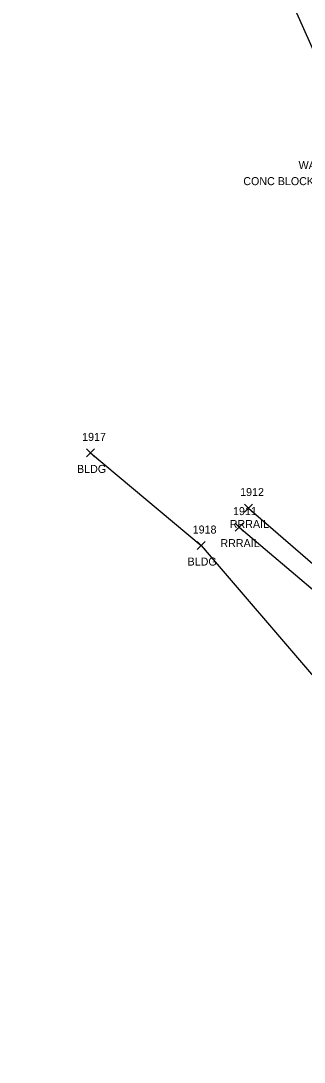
# Model space of a CAD drawing. Extents: x 1635588 to 1637550, y 621583 to 623638.
# Drawn here: x 1636590.6 to 1636661.5, y 622165 to 622425.2 of the extents above; entities that cross this region are included whole.
import ezdxf

# ---------------------------------------------------------------- set-up
doc = ezdxf.new("R2010")
doc.units = 0
for name, color, linetype in [('L_A', 7, 'Continuous'), ('L_C', 7, 'Continuous'), ('L_I', 7, 'Continuous'), ('L_TIC', 7, 'Continuous'), ('LBC', 7, 'Continuous'), ('R_A', 7, 'Continuous'), ('R_I', 7, 'Continuous'), ('R_TIC', 7, 'Continuous'), ('RR', 7, 'Continuous')]:
    doc.layers.add(name, color=color, linetype=linetype)

msp = doc.modelspace()

# ---------------------------------------------------------------- linework, layer by layer
at = {"layer": 'L_TIC'}
for points in [[(1636607.08, 622316.23), (1636609.08, 622318.23)], [(1636609.08, 622316.23), (1636607.08, 622318.23)], [(1636634.72, 622293.09), (1636636.72, 622295.09)], [(1636636.72, 622293.09), (1636634.72, 622295.09)]]:
    msp.add_lwpolyline(points, dxfattribs=at)
at = {"layer": 'LBC'}
msp.add_lwpolyline([(1636608.08, 622317.23), (1636635.72, 622294.09), (1636721.42, 622194.15), (1636719.71, 622191.27), (1636742.59, 622170.36)], dxfattribs=at)
at = {"layer": 'R_TIC'}
for points in [[(1636646.57, 622302.46), (1636648.57, 622304.46)], [(1636648.57, 622302.46), (1636646.57, 622304.46)], [(1636644.23, 622297.69), (1636646.23, 622299.69)], [(1636646.23, 622297.69), (1636644.23, 622299.69)]]:
    msp.add_lwpolyline(points, dxfattribs=at)
at = {"layer": 'RR'}
for points in [[(1636590.62, 622643.06), (1636603.96, 622594.72), (1636620.27, 622536.36), (1636632.07, 622498.45), (1636643.29, 622466.78), (1636655.39, 622436.56), (1636668.93, 622406.09), (1636689.56, 622363.97), (1636710.33, 622322.06), (1636729.55, 622284.99), (1636743.57, 622259.26), (1636761.55, 622228.91), (1636778.55, 622203.2), (1636800.49, 622173.78), (1636817.8, 622151.9), (1636836.04, 622130.9), (1636862.72, 622101.67), (1636929.58, 622028.72), (1636988.41, 621964.46), (1637027.08, 621922.66), (1637047.82, 621899.75)], [(1636647.57, 622303.46), (1636681.53, 622274.07), (1636698.35, 622258.6), (1636736.07, 622216.66), (1636772.81, 622171.31), (1636793.48, 622145.5), (1636799.12, 622138.4), (1636815.41, 622118.42), (1636845.94, 622085.12), (1636908.55, 622026.21), (1636983.07, 621959.74), (1637027.08, 621922.66), (1637050.39, 621902.14), (1637074.4, 621880.01)], [(1636645.23, 622298.69), (1636678.25, 622270.68), (1636695.49, 622253.83), (1636732.46, 622213.3), (1636769.51, 622167.71), (1636788.83, 622143.09), (1636795.06, 622135.55), (1636811.52, 622115.54), (1636841.96, 622081.95), (1636905.16, 622022.78), (1636979.87, 621956.02), (1637024.02, 621918.73), (1637048, 621897.73), (1637071.19, 621876.23)]]:
    msp.add_lwpolyline(points, dxfattribs=at)

# ---------------------------------------------------------------- texts
at = {"layer": 'L_A'}
for s, p in [('WALLS', (1636660.06, 622388.13)), ('BLDG', (1636604.67, 622312.23)), ('BLDG', (1636632.31, 622289.09))]:
    msp.add_text(s, height=2, dxfattribs=at).set_placement(p)
at = {"layer": 'L_C'}
msp.add_text('CONC BLOCKS RETAINING', height=2, dxfattribs=at).set_placement((1636646.24, 622384.13))
at = {"layer": 'L_I'}
for s, p in [('1917', (1636605.95, 622320.23)), ('1918', (1636633.59, 622297.09))]:
    msp.add_text(s, height=2, dxfattribs=at).set_placement(p)
at = {"layer": 'R_A'}
for p in [(1636642.86, 622298.46), (1636640.52, 622293.69)]:
    msp.add_text('RRRAIL', height=2, dxfattribs=at).set_placement(p)
at = {"layer": 'R_I'}
for s, p in [('1912', (1636645.45, 622306.46)), ('1911', (1636643.67, 622301.69))]:
    msp.add_text(s, height=2, dxfattribs=at).set_placement(p)

doc.saveas('drawing.dxf')
